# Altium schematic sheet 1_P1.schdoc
size 307 x 218 mm; Symbol: Drawing-Symbol_A4; Device: Drawing-Symbol_A4; @Project Name: GeniusGateway; @Page Count: 1; @Update Date: 2025-08-11; @Create Date: 2025-07-15; @Schematic Name: Main; @Page No: 1; @Page Name: P1; Company: EasyEDA.com; Version: V1.1; Page Size: A4; @Create Time: 21:34:21; @Update Time: 16:36:52; Width: 1170; Height: 825; Region Start: 1; X Region Count: 6; Y Region Count: 4; Blade Width: 10; Title Block Position: 3; @Board Name: Main
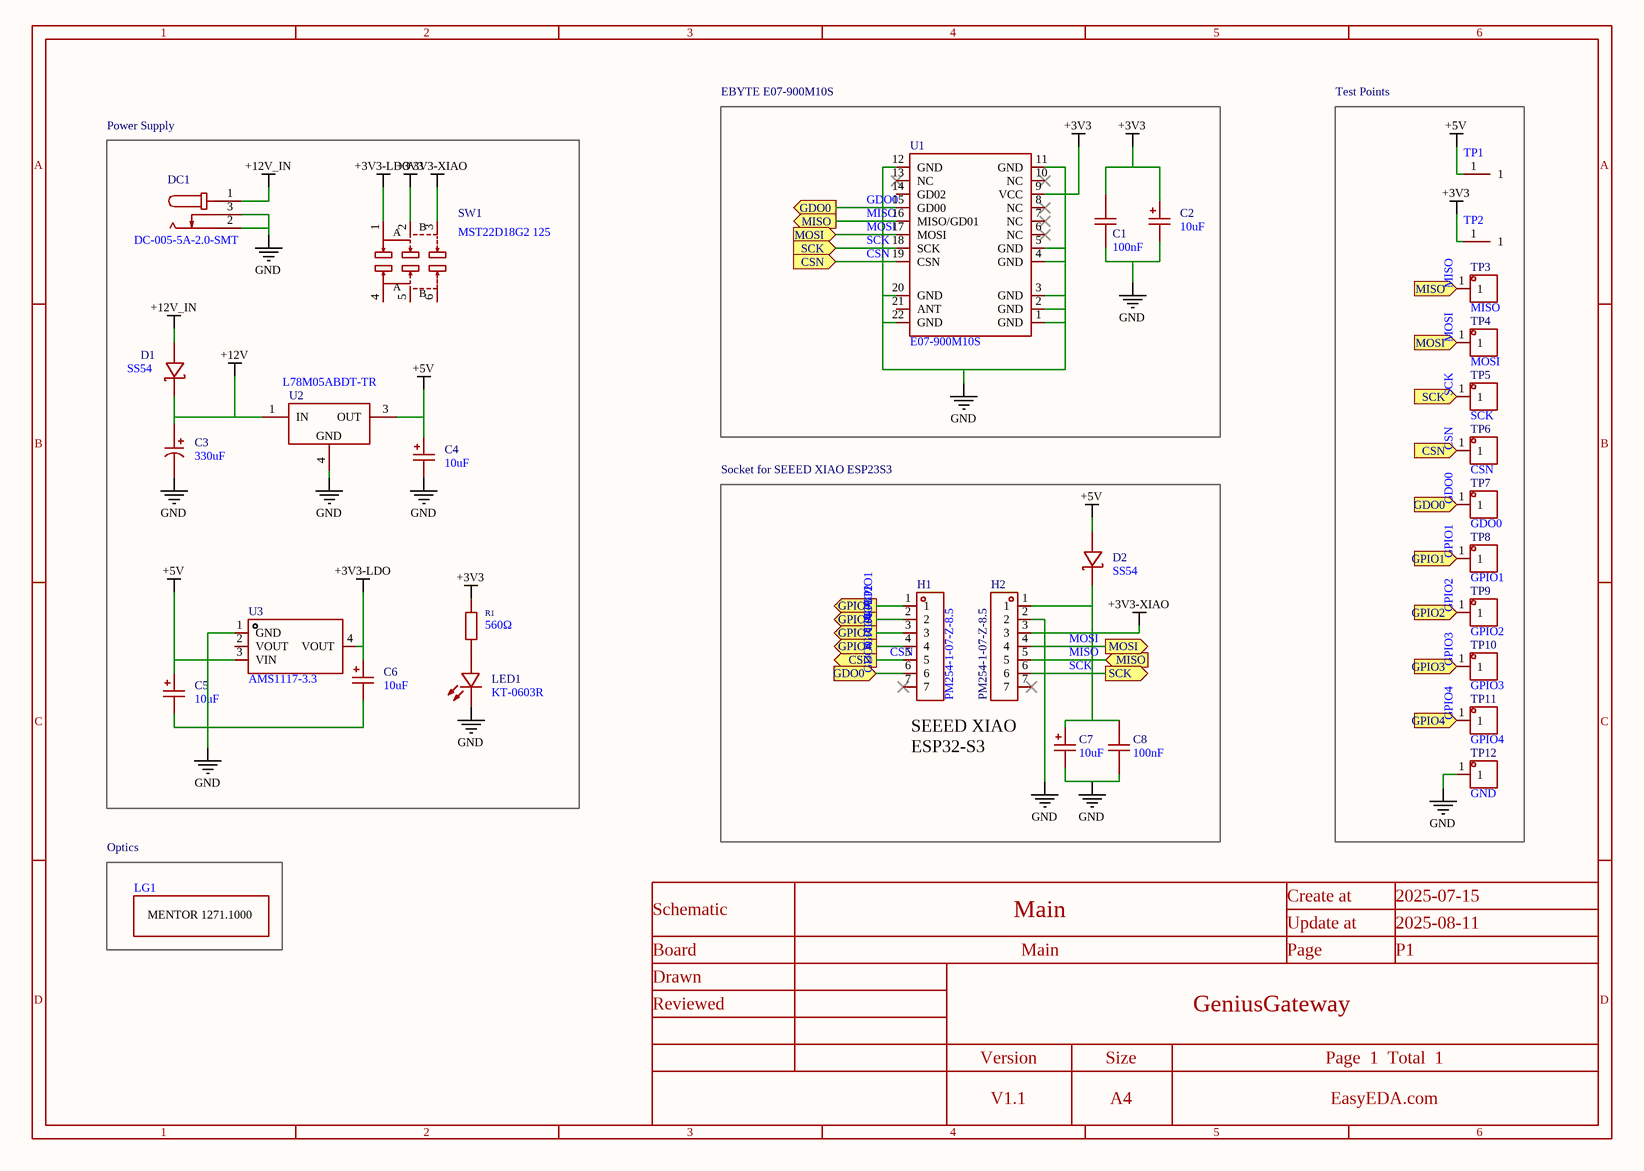
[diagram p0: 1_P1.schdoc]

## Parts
C1  100nF  [C0805]
C2  10uF  [CAP-SMD_L3.2-W1.6-RD-C7171]
C3  330uF  [CAP-SMD_BD6.3-L6.6-W6.6-LS7.6-RD]
C4  10uF  [CAP-SMD_L3.2-W1.6-RD-C7171]
C5  10uF  [CAP-SMD_L3.2-W1.6-RD-C7171]
C6  10uF  [CAP-SMD_L3.2-W1.6-RD-C7171]
C7  10uF  [CAP-SMD_L3.2-W1.6-RD-C7171]
C8  100nF  [C0805]
D1  SS54  [SMA_L4.4-W2.8-LS5.4-R-RD]
D2  SS54  [SMA_L4.4-W2.8-LS5.4-R-RD]
DC1  DC-005-5A-2.0-SMT  [DC-IN-TH_DC-005-5A-2.0-SMT]
H1  PM254-1-07-Z-8.5  [HDR-TH_7P-P2.54-V-F]
H2  PM254-1-07-Z-8.5  [HDR-TH_7P-P2.54-V-F]
LED1  KT-0603R  [LED0603-RD]
LG1  (no value)  [MENTOR-1271.1000]
R1  560Ω  [R0603]
SW1  MST22D18G2 125  [SW-SMD_MST22D18G2]
TP1  +5V  [Testpoint_SMD_R1.5_Border]  (value not drawn)
TP2  3V3  [Testpoint_SMD_R1.5_Border]  (value not drawn)
TP3  MISO  [TEST-TH_BD2.54-P1.39]
TP4  MOSI  [TEST-TH_BD2.54-P1.39]
TP5  SCK  [TEST-TH_BD2.54-P1.39]
TP6  CSN  [TEST-TH_BD2.54-P1.39]
TP7  GDO0  [TEST-TH_BD2.54-P1.39]
TP8  GPIO1  [TEST-TH_BD2.54-P1.39]
TP9  GPIO2  [TEST-TH_BD2.54-P1.39]
TP10  GPIO3  [TEST-TH_BD2.54-P1.39]
TP11  GPIO4  [TEST-TH_BD2.54-P1.39]
TP12  GND  [TEST-TH_BD2.54-P1.39]
U1  E07-900M10S  [WIRELM-SMD_22P-L20.0-W14.0-P1.27-BR]
U2  L78M05ABDT-TR  [TO-252-2_L6.5-W6.1-P4.58-LS10.0-TL]
U3  AMS1117-3.3  [SOT-223-3_L6.5-W3.4-P2.30-LS7.0-BR]

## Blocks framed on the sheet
EBYTE E07-900M10S: C1 C2 U1
Test Points: TP1-TP12
Power Supply: C3-C6 D1 DC1 LED1 R1 SW1 U2 U3
Socket for SEEED XIAO ESP23S3: C7 C8 D2 H1 H2
Optics: LG1

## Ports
CSN (in), CSN (out), GDO0 (in), GDO0 (out), GPIO1 (in), GPIO1 (out), GPIO2 (in), GPIO2 (out), GPIO3 (in), GPIO3 (out), GPIO4 (in), GPIO4 (out), MISO (in), MISO (out), MOSI (in), MOSI (out), SCK (in), SCK (out)

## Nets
+3V3: C1.2 C2.1 R1.2 SW1.2 TP2.1 U1.9(VCC)
+3V3-LDO: C6.1 SW1.1 U3.4(VOUT)
+3V3-XIAO: H2.3 SW1.3
+5V: C4.1 C5.1 D2.1(A) TP1.1 U2.3(OUT) U3.3(VIN)
+12V: C3.1 D1.2(K) U2.1(IN)
+12V_IN: D1.1(A) DC1.1
GND: C1.1 C2.2 C3.2 C4.2 C5.2 C6.2 C7.2 C8.1 DC1.2 DC1.3 H2.2 LED1.1(K) TP12.1 U1.1(GND) U1.2(GND) U1.3(GND) U1.4(GND) U1.5(GND) U1.11(GND) U1.12(GND) U1.20(GND) U1.22(GND) U2.4(GND) U3.1(GND)
CSN: H1.5 TP6.1 U1.19(CSN) ; port CSN
GDO0: H1.6 TP7.1 U1.15(GD00) ; port GDO0
GPIO1: H1.1 TP8.1 ; port GPIO1
GPIO2: H1.2 TP9.1 ; port GPIO2
GPIO3: H1.3 TP10.1 ; port GPIO3
GPIO4: H1.4 TP11.1 ; port GPIO4
MISO: H2.5 TP3.1 U1.16(MISO/GD01) ; port MISO
MOSI: H2.4 TP4.1 U1.17(MOSI) ; port MOSI
SCK: H2.6 TP5.1 U1.18(SCK) ; port SCK
NetC7_1: C7.1 C8.2 D2.2(K) H2.1
NetLED1_2: LED1.2(A) R1.1

Not connected (* = marked no-connect by the designer): H1 7*; H2 7*; SW1 4 5 6; U1 6(NC)* 7(NC)* 8(NC)* 10(NC)* 13(NC)* 14(GD02) 21(ANT); U3 2(VOUT)

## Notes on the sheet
- SEEED XIAO
  ESP32-S3

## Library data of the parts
C1 C8 = CC0805KRX7R9BB104: Manufacturer: YAGEO(国巨); Add into BOM: yes; Tolerance: ±10%
C2 C4-C7 = TAJA106K016RNJ: Manufacturer: Kyocera AVX; Add into BOM: yes; Tolerance: ±10%; Voltage Rating: 16V; Equivalent Series Resistance(ESR): 3Ω@100kHz
C3 = 189RV0016: Manufacturer: KNSCHA(科尼盛); Add into BOM: yes; Tolerance: ±20%; Ripple Current: 600mA@100KHz; Equivalent Series Resistance(ESR): 160mΩ@100KHz
D1 D2 = SS54_C22452: Manufacturer: MDD(辰达半导体); Add into BOM: yes; Diode Configuration: Independent Type; Forward Voltage (Vf@If): 550mV@5A; Reverse Voltage (Vr): 40V; Rectified Current: 5A; Reverse Leakage Current (Ir): 1mA@40V
DC1 = DC-005-5A-2.0-SMT: Manufacturer: XKB Connection(中国星坤); Add into BOM: yes; Connector Type: DC Power Receptacle; Inside Contact Diameter: 2mm; Outside Contact Diameter: 6.6mm; Current Rating (Max): 2.5A; Voltage Rating (Max): 24V
H1 H2 = PM254-1-07-Z-8.5: Manufacturer: HCTL(华灿天禄); Add into BOM: yes; Holes Structure: 1x7P; Pitch: 2.54mm; Circular Hole / Square Hole: Square Holes; Number of Holes: 7P; Current Rating (Max): 3A; Holes Direction: Top; Soldering Temperature(Max): 260℃@5S
LED1 = KT-0603R: Manufacturer: KENTO; Add into BOM: yes; Emitted Color: Red
LG1 = Lightguide 1: Add into BOM: no; Convert to PCB: yes
R1 = 0603WAF5600T5E: Manufacturer: UNI-ROYAL(厚声); Add into BOM: yes; Tolerance: ±1%; Temperature Coefficient: ±100ppm/℃
SW1 = MST22D18G2 125: Manufacturer: SHOU HAN(首韩); Add into BOM: yes; Circuit: DPDT; Pin Style: Gull Wing; Actuator Color: Black; Current Rating (DC): 100mA; Voltage Rating (DC): 12V; Mechanical Life: 1万次
TP1 TP2 = Testpoint1: Add into BOM: no; Convert to PCB: yes
TP3-TP12 = 5001_C238122: Manufacturer: Keystone; Symbol: 5001; Add into BOM: yes; Connector Type: Pin type (through board); Plastic Color: Black; Board Space (Diameter φ/ Length x Width): 2.5mm
U1 = E07-900M10S: Add into BOM: yes
U2 = L78M05ABDT-TR: Manufacturer: ST(意法半导体); Add into BOM: yes; Output Type: Fixed; Maximum Input Voltage: 35V; Output Voltage: 5V; Output Current: 500mA; Power Supply Rejection Ratio (PSRR): 62dB@(120Hz); standby current: 6mA; Output Polarity: Positive electrode; Number of Outputs: 1
U3 = AMS1117-3.3_C6186: Manufacturer: AMS; Add into BOM: yes; Output Type: Fixed; Voltage - Supply: 16V; Output Voltage: 3.3V; Output Current: 1A; Power Supply Rejection Ratio (PSRR): 72dB@(120Hz); Voltage Dropout: 1.1V@(800mA); standby current: 5mA; Output Configuration: Positive; Number of Outputs: 1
